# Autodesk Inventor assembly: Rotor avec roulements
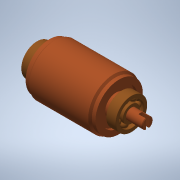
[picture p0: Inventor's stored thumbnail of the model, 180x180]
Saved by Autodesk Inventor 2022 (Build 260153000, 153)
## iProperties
Created: 2005-01
Part Number: Rotor avec roulements
Document SubType Name: Assembly
Designer: lolo (Laurent Moretti)
Control State: 0
Master: False
Checked Out: False
Shininess: 64.0
Length Units: 11269
Angle Units: 11279
Time Units: 11290
Mass Units: 11283
Length Display Precision: 3
Angle Display Precision: 2
Compacted: True
Density: 0.0
Volumn: 0.0
Area: 0.0
PropertySet Name: Model Information
Author: lolo (Laurent Moretti)
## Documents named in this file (3)
- C:\Travail\Moteur électrique\Rotor avec roulements\Rotor avec roulements.iam
- C:\Travail\Moteur électrique\Rotor avec roulements\Rotor nu.ipt
- C:\Travail\Moteur électrique\Rotor avec roulements\Roulement.ipt
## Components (3 placed, 2 different names)
1. Rotor nu:1 — Logement:1, Logement:2
2. Roulement:1 — Logement:1
3. Roulement:2 — Logement:2
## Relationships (2: Insert 2)
- Logement:1 [Insert]: Rotor nu:1 ↔ Roulement:1
- Logement:2 [Insert]: Rotor nu:1 ↔ Roulement:2
